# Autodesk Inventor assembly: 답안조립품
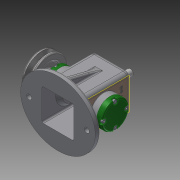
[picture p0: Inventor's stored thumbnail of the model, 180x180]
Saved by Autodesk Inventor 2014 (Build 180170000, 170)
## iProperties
Created: 2017-07
Part Number: 답안조립품
Document SubType Name: Weldment
Designer: 406-3333
Weld Material: Welded Aluminum-6061
Author: 406-3333
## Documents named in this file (15)
- C:\Users\406-3333\Desktop\470707V1013\답안조립품.iam
- C:\Users\406-3333\Desktop\470707V1013\편심축.ipt
- C:\Users\406-3333\Desktop\470707V1013\키 4 x 4 x 10.ipt
- C:\Users\406-3333\Desktop\470707V1013\베어링 12 x 32 x 10.ipt
- C:\Users\406-3333\Desktop\470707V1013\본체.ipt
- C:\Users\406-3333\Desktop\470707V1013\앞커버.ipt
- C:\Users\406-3333\Desktop\470707V1013\뒤커버.ipt
- C:\Users\406-3333\Desktop\470707V1013\볼트 M4 x 12.ipt
- C:\Users\406-3333\Desktop\470707V1013\V벨트풀리.ipt
- C:\Users\406-3333\Desktop\470707V1013\오일실 12 25 7.ipt
- C:\Users\406-3333\Desktop\470707V1013\슬라이드.ipt
- C:\Users\406-3333\Desktop\470707V1013\핀 5 x 18.ipt
- C:\Users\406-3333\Desktop\470707V1013\고정핀 1.2 x  8.ipt
- C:\Users\406-3333\Desktop\470707V1013\링크.ipt
- C:\Users\406-3333\Desktop\470707V1013\부시.ipt
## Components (3 placed, 3 different names)
1. V벨트풀리:1 — 각도:3
2. 핀 5 x 18:1
3. 고정핀 1.2 x  8:1
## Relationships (1: Angle 1)
- 각도:3 [Angle]: V벨트풀리:1
